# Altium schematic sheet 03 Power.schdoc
size 400 x 277 mm; Device: default420x297; Symbol: default420x297; Name: default420x297; Size: "A3"; Id: /; File: 03 Power; Sheet: /
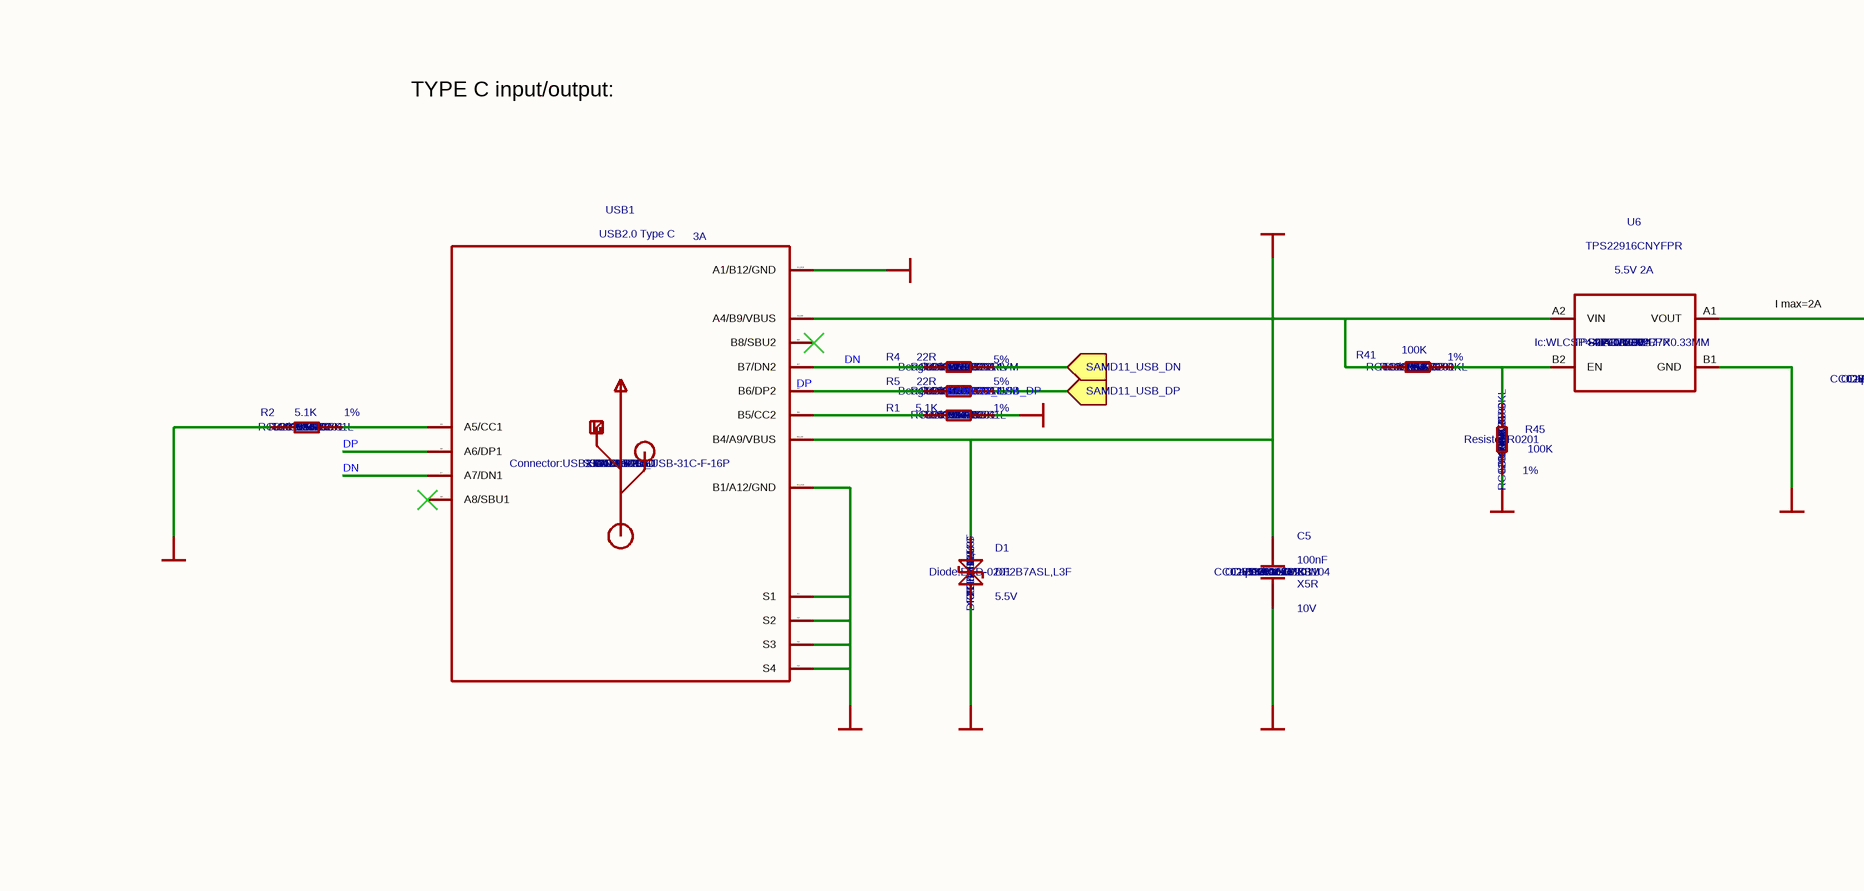
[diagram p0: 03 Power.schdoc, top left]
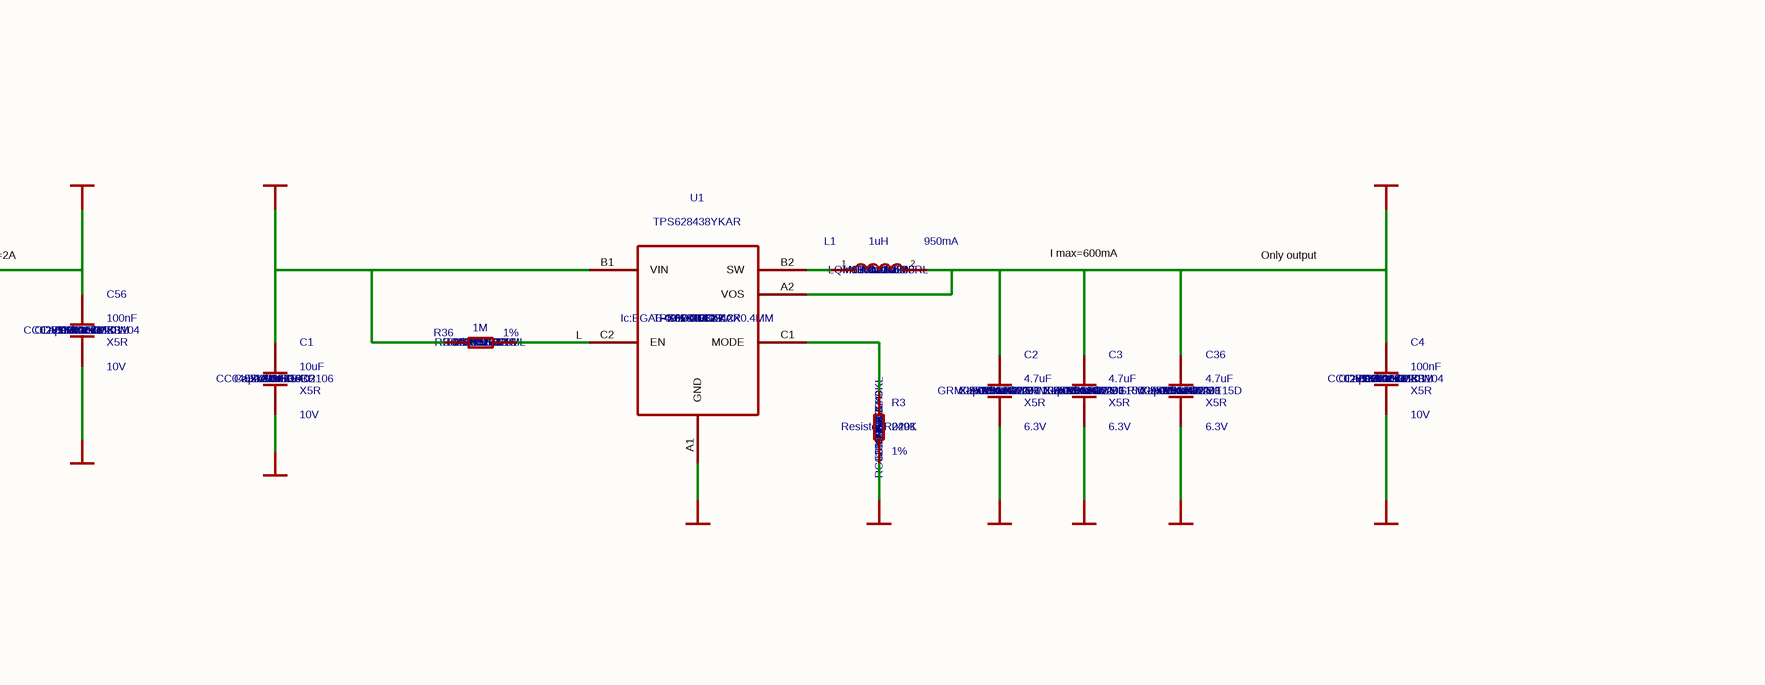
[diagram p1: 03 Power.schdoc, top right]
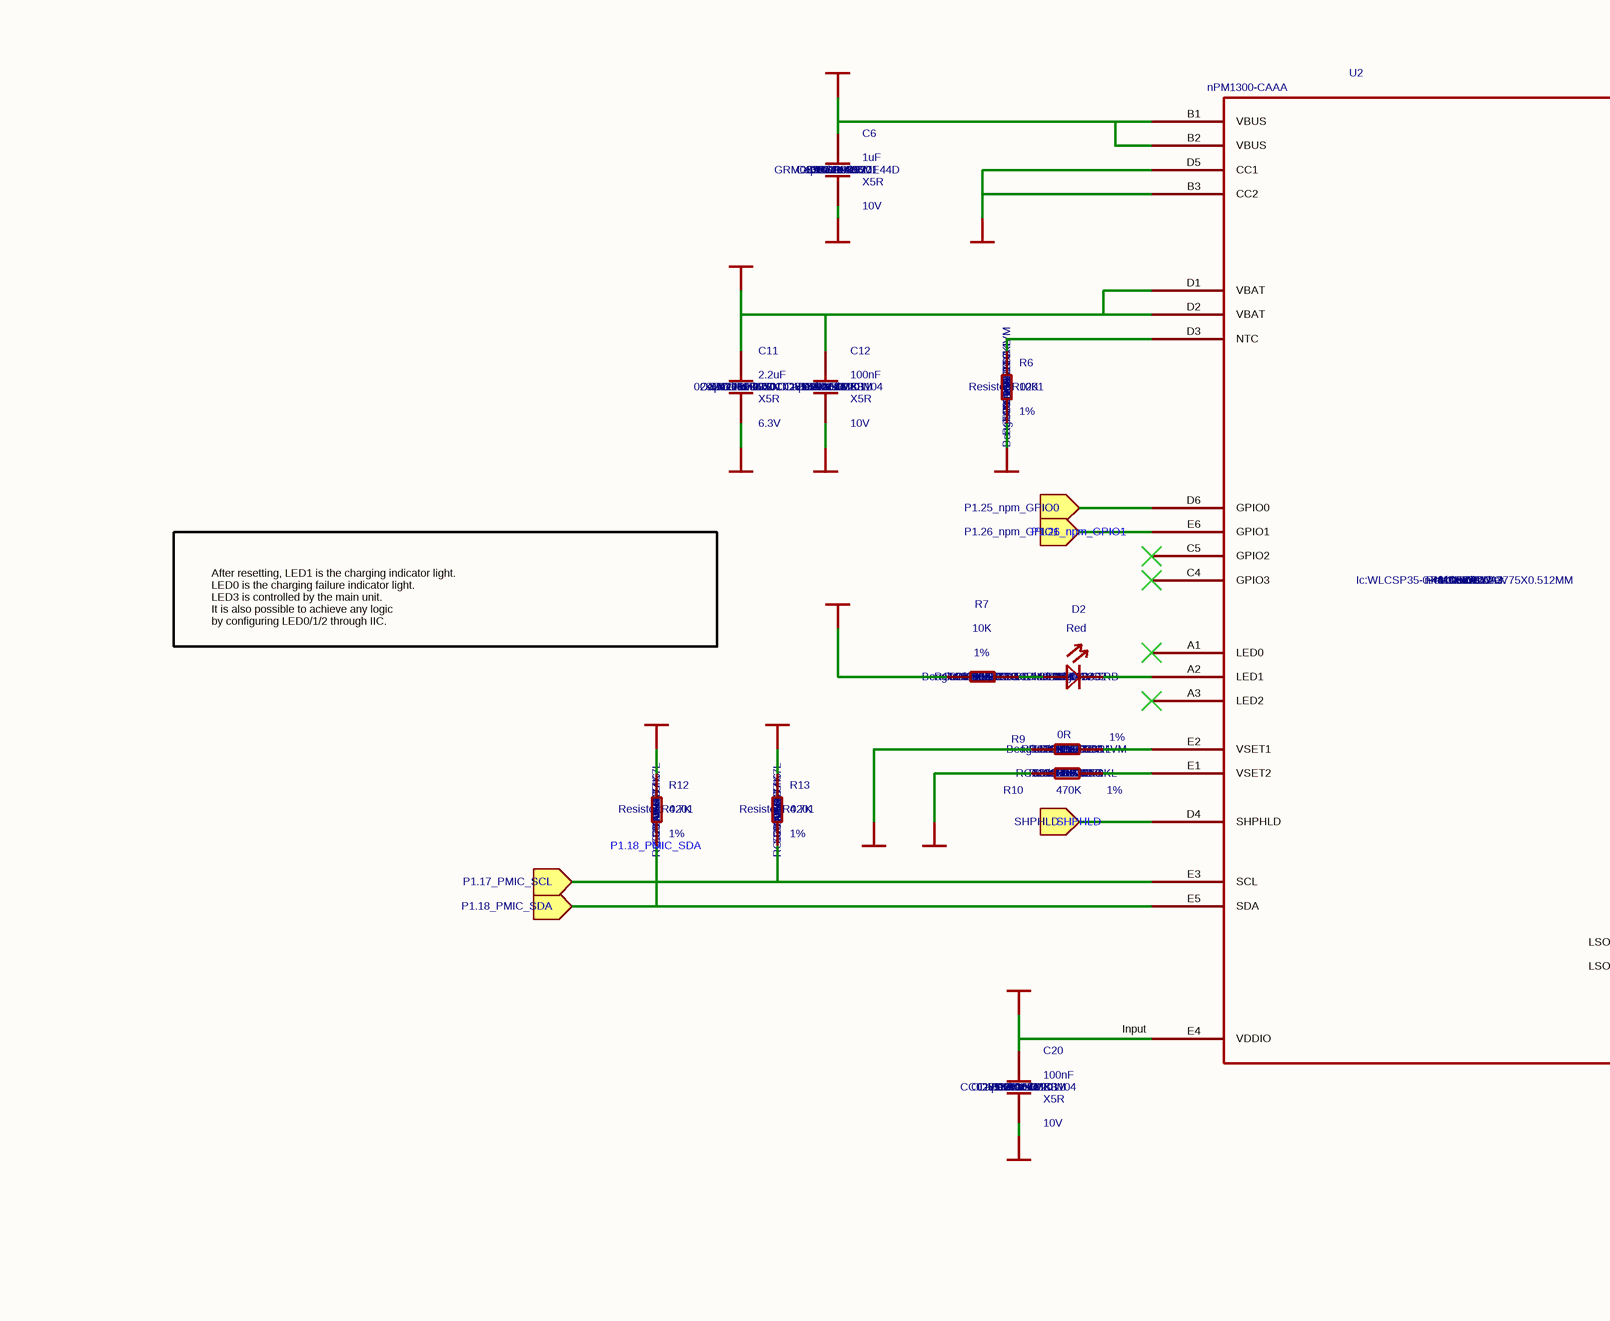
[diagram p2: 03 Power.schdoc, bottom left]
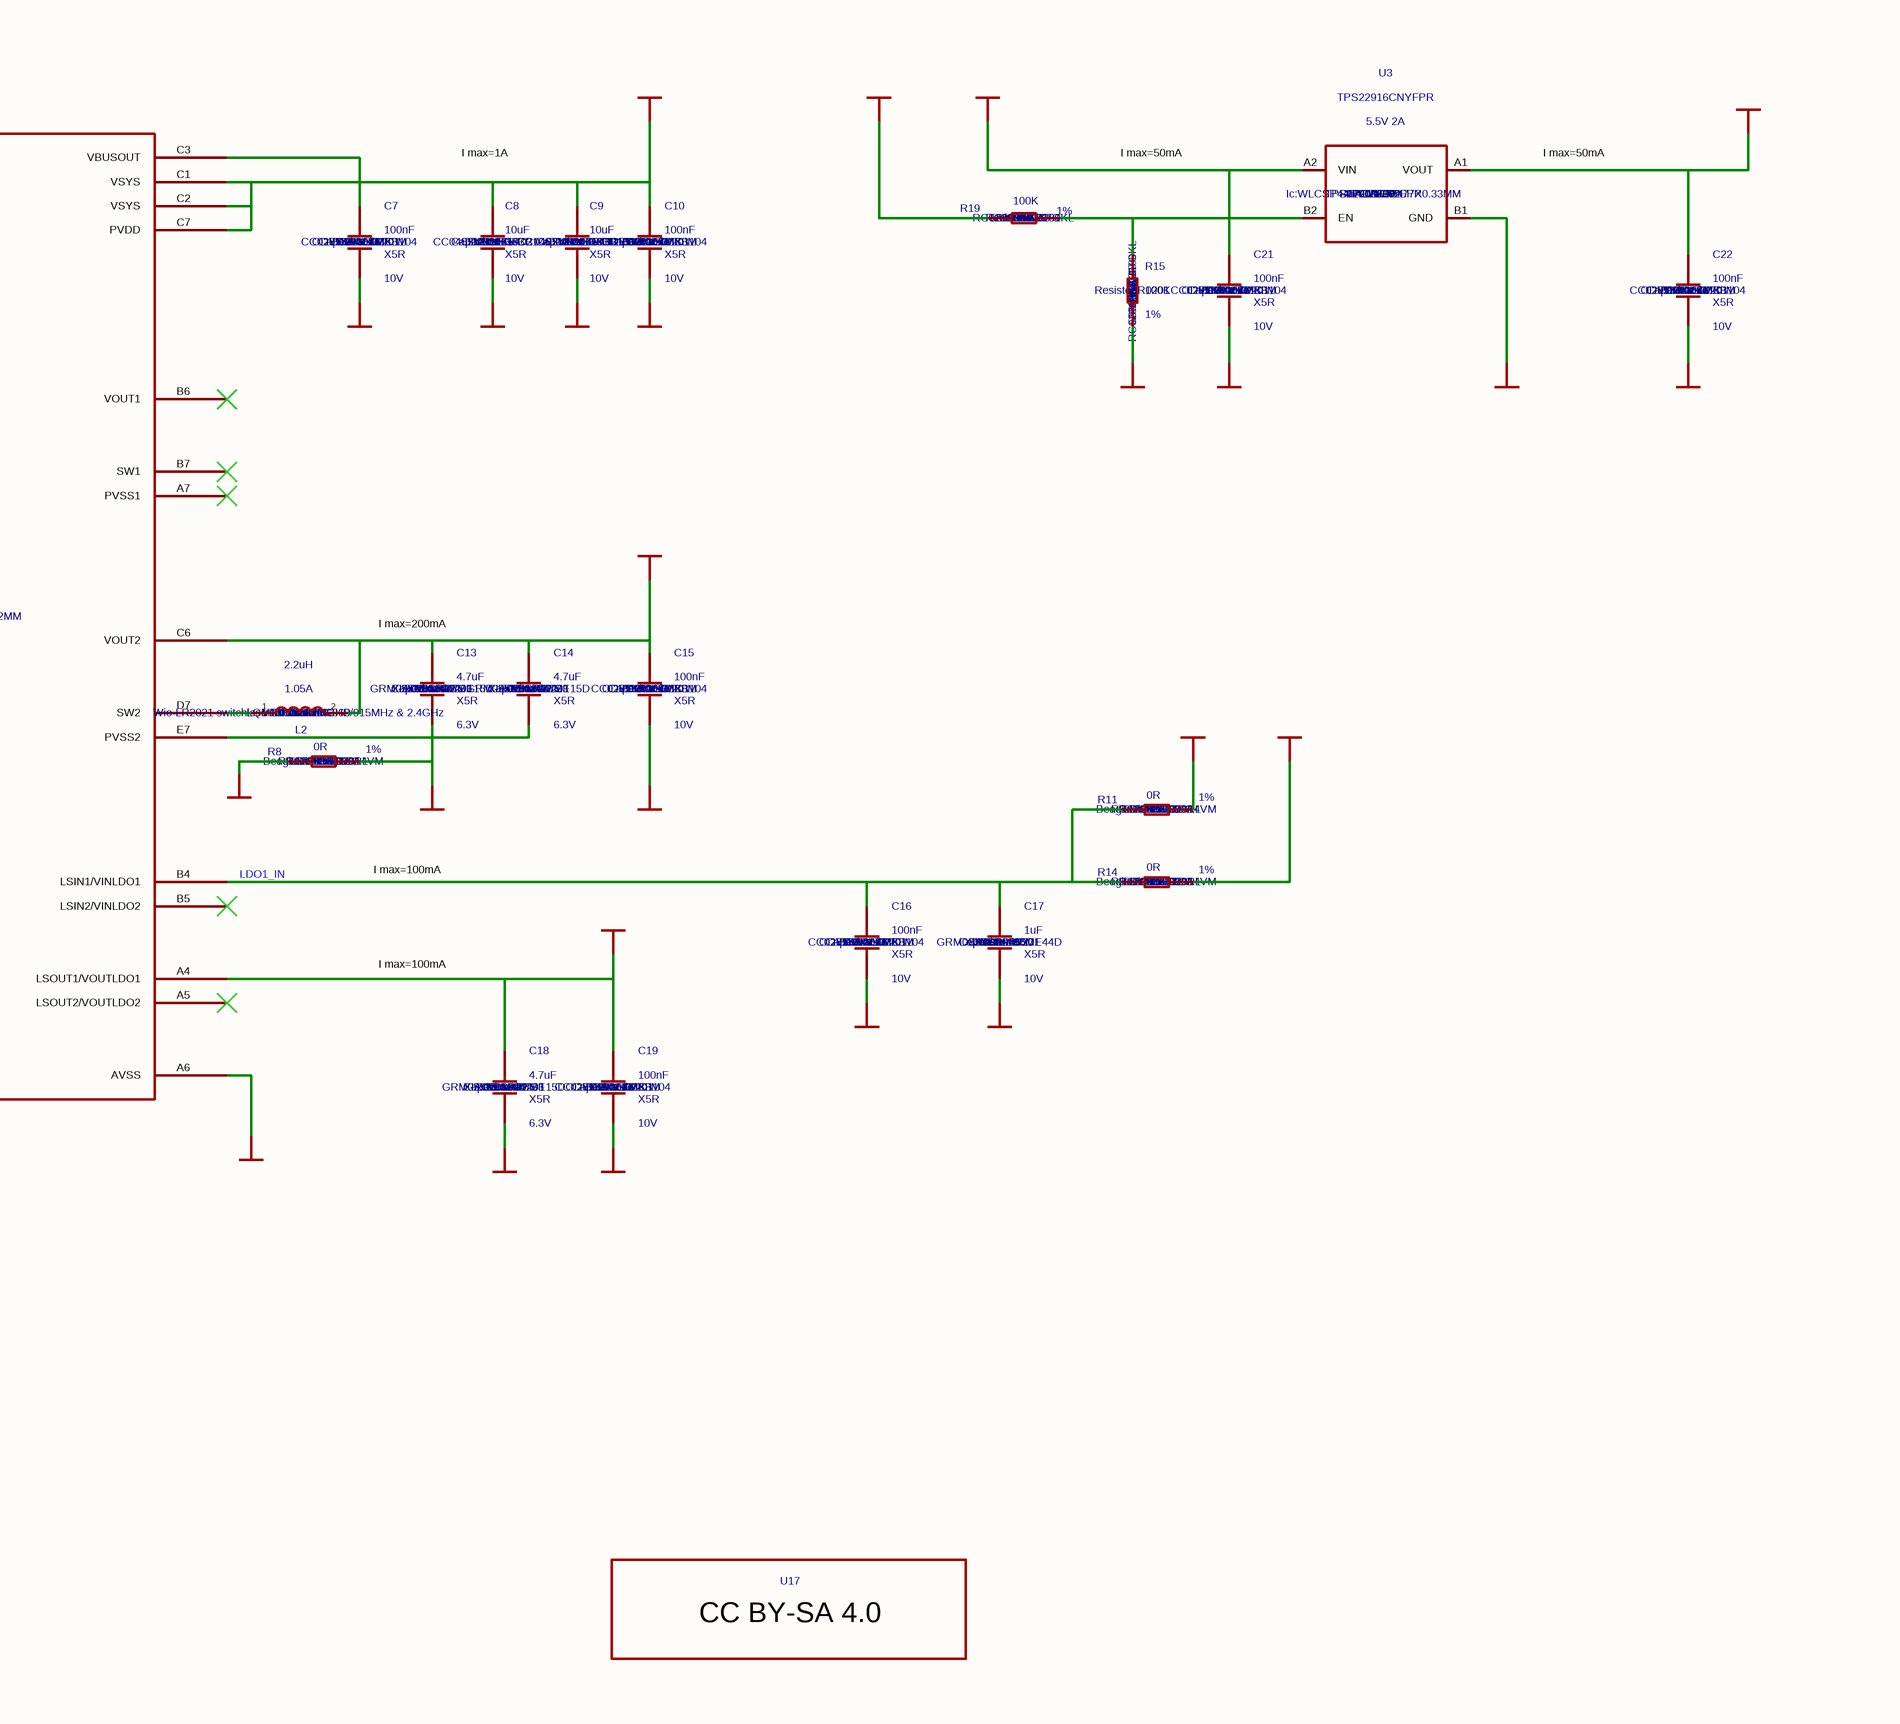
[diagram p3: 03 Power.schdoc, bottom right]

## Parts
C1  value 10uF  Manufacturer: YAGEO  MPN: CC0402MRX5R6BB106  SKU: 302010519  Dielectric: X5R  Voltage Rating: 10V  Status: XIAO  Temperature: -55°C to 85°C  [Capacitor:C0402]  (hidden comment: Seeed_libdb_Capacitors/CA40210UF0-TZJGY3)
C2  value 4.7uF  Manufacturer: Murata  MPN: GRM035R60J475ME15D  SKU: 302013247  Dielectric: X5R  Part Type: Ceramic  Voltage Rating: 6.3V  Status: XIAO ESP32 S3  Temperature: -55°C to 85°C  [Capacitor:C0201]  (hidden comment: Seeed_libdb_Capacitors/CA20147UF0-SN7236)
C3  value 4.7uF  Manufacturer: Murata  MPN: GRM035R60J475ME15D  SKU: 302013247  Dielectric: X5R  Part Type: Ceramic  Voltage Rating: 6.3V  Status: XIAO ESP32 S3  Temperature: -55°C to 85°C  [Capacitor:C0201]  (hidden comment: Seeed_libdb_Capacitors/CA20147UF0-SN7236)
C4  value 100nF  Manufacturer: YAGEO  MPN: CC0201KRX5R6BB104  SKU: 302010271  Dielectric: X5R  Part Type: Ceramic  Voltage Rating: 10V  Status: ODYSSEY-i.MX8M  Temperature: -55°C to 85°C  [Capacitor:C0201]  (hidden comment: Seeed_libdb_Capacitors/CA201100NF-SQS4XQ)
C5  value 100nF  Manufacturer: YAGEO  MPN: CC0201KRX5R6BB104  SKU: 302010271  Dielectric: X5R  Part Type: Ceramic  Voltage Rating: 10V  Status: ODYSSEY-i.MX8M  Temperature: -55°C to 85°C  [Capacitor:C0201]  (hidden comment: Seeed_libdb_Capacitors/CA201100NF-SQS4XQ)
C6  value 1uF  Manufacturer: muRata  MPN: GRM033R61A105ME44D  SKU: 302010730  Dielectric: X5R  Part Type: Ceramic  Voltage Rating: 10V  Status: XIAO RP2350  Temperature: -55°C to 85°C  [Capacitor:C0201]  (hidden comment: Seeed_libdb_Capacitors/CA2011UF00-7ESDY3)
C7  value 100nF  Manufacturer: YAGEO  MPN: CC0201KRX5R6BB104  SKU: 302010271  Dielectric: X5R  Part Type: Ceramic  Voltage Rating: 10V  Status: ODYSSEY-i.MX8M  Temperature: -55°C to 85°C  [Capacitor:C0201]  (hidden comment: Seeed_libdb_Capacitors/CA201100NF-SQS4XQ)
C8  value 10uF  Manufacturer: YAGEO  MPN: CC0402MRX5R6BB106  SKU: 302010519  Dielectric: X5R  Voltage Rating: 10V  Status: XIAO  Temperature: -55°C to 85°C  [Capacitor:C0402]  (hidden comment: Seeed_libdb_Capacitors/CA40210UF0-TZJGY3)
C9  value 10uF  Manufacturer: YAGEO  MPN: CC0402MRX5R6BB106  SKU: 302010519  Dielectric: X5R  Voltage Rating: 10V  Status: XIAO  Temperature: -55°C to 85°C  [Capacitor:C0402]  (hidden comment: Seeed_libdb_Capacitors/CA40210UF0-TZJGY3)
C10  value 100nF  Manufacturer: YAGEO  MPN: CC0201KRX5R6BB104  SKU: 302010271  Dielectric: X5R  Part Type: Ceramic  Voltage Rating: 10V  Status: ODYSSEY-i.MX8M  Temperature: -55°C to 85°C  [Capacitor:C0201]  (hidden comment: Seeed_libdb_Capacitors/CA201100NF-SQS4XQ)
C11  value 2.2uF  Manufacturer: FH  MPN: 0201X225M6R3NT  SKU: 302012960  Dielectric: X5R  Part Type: Ceramic  Voltage Rating: 6.3V  Status: XIAO_RP2350  Temperature: -55°C to 85°C  [Capacitor:C0201]  (hidden comment: Seeed_libdb_Capacitors/CA20122UF0-RZ5XFV)
C12  value 100nF  Manufacturer: YAGEO  MPN: CC0201KRX5R6BB104  SKU: 302010271  Dielectric: X5R  Part Type: Ceramic  Voltage Rating: 10V  Status: ODYSSEY-i.MX8M  Temperature: -55°C to 85°C  [Capacitor:C0201]  (hidden comment: Seeed_libdb_Capacitors/CA201100NF-SQS4XQ)
C13  value 4.7uF  Manufacturer: Murata  MPN: GRM035R60J475ME15D  SKU: 302013247  Dielectric: X5R  Part Type: Ceramic  Voltage Rating: 6.3V  Status: XIAO ESP32 S3  Temperature: -55°C to 85°C  [Capacitor:C0201]  (hidden comment: Seeed_libdb_Capacitors/CA20147UF0-SN7236)
C14  value 4.7uF  Manufacturer: Murata  MPN: GRM035R60J475ME15D  SKU: 302013247  Dielectric: X5R  Part Type: Ceramic  Voltage Rating: 6.3V  Status: XIAO ESP32 S3  Temperature: -55°C to 85°C  [Capacitor:C0201]  (hidden comment: Seeed_libdb_Capacitors/CA20147UF0-SN7236)
C15  value 100nF  Manufacturer: YAGEO  MPN: CC0201KRX5R6BB104  SKU: 302010271  Dielectric: X5R  Part Type: Ceramic  Voltage Rating: 10V  Status: ODYSSEY-i.MX8M  Temperature: -55°C to 85°C  [Capacitor:C0201]  (hidden comment: Seeed_libdb_Capacitors/CA201100NF-SQS4XQ)
C16  value 100nF  Manufacturer: YAGEO  MPN: CC0201KRX5R6BB104  SKU: 302010271  Dielectric: X5R  Part Type: Ceramic  Voltage Rating: 10V  Status: ODYSSEY-i.MX8M  Temperature: -55°C to 85°C  [Capacitor:C0201]  (hidden comment: Seeed_libdb_Capacitors/CA201100NF-SQS4XQ)
C17  value 1uF  Manufacturer: muRata  MPN: GRM033R61A105ME44D  SKU: 302010730  Dielectric: X5R  Part Type: Ceramic  Voltage Rating: 10V  Status: XIAO RP2350  Temperature: -55°C to 85°C  [Capacitor:C0201]  (hidden comment: Seeed_libdb_Capacitors/CA2011UF00-7ESDY3)
C18  value 4.7uF  Manufacturer: Murata  MPN: GRM035R60J475ME15D  SKU: 302013247  Dielectric: X5R  Part Type: Ceramic  Voltage Rating: 6.3V  Status: XIAO ESP32 S3  Temperature: -55°C to 85°C  [Capacitor:C0201]  (hidden comment: Seeed_libdb_Capacitors/CA20147UF0-SN7236)
C19  value 100nF  Manufacturer: YAGEO  MPN: CC0201KRX5R6BB104  SKU: 302010271  Dielectric: X5R  Part Type: Ceramic  Voltage Rating: 10V  Status: ODYSSEY-i.MX8M  Temperature: -55°C to 85°C  [Capacitor:C0201]  (hidden comment: Seeed_libdb_Capacitors/CA201100NF-SQS4XQ)
C20  value 100nF  Manufacturer: YAGEO  MPN: CC0201KRX5R6BB104  SKU: 302010271  Dielectric: X5R  Part Type: Ceramic  Voltage Rating: 10V  Status: ODYSSEY-i.MX8M  Temperature: -55°C to 85°C  [Capacitor:C0201]  (hidden comment: Seeed_libdb_Capacitors/CA201100NF-SQS4XQ)
C21  value 100nF  Manufacturer: YAGEO  MPN: CC0201KRX5R6BB104  SKU: 302010271  Dielectric: X5R  Part Type: Ceramic  Voltage Rating: 10V  Status: ODYSSEY-i.MX8M  Temperature: -55°C to 85°C  [Capacitor:C0201]  (hidden comment: Seeed_libdb_Capacitors/CA201100NF-SQS4XQ)
C22  value 100nF  Manufacturer: YAGEO  MPN: CC0201KRX5R6BB104  SKU: 302010271  Dielectric: X5R  Part Type: Ceramic  Voltage Rating: 10V  Status: ODYSSEY-i.MX8M  Temperature: -55°C to 85°C  [Capacitor:C0201]  (hidden comment: Seeed_libdb_Capacitors/CA201100NF-SQS4XQ)
C36  value 4.7uF  Manufacturer: Murata  MPN: GRM035R60J475ME15D  SKU: 302013247  Dielectric: X5R  Part Type: Ceramic  Voltage Rating: 6.3V  Status: XIAO ESP32 S3  Temperature: -55°C to 85°C  [Capacitor:C0201]  (hidden comment: Seeed_libdb_Capacitors/CA20147UF0-SN7236)
C56  value 100nF  Manufacturer: YAGEO  MPN: CC0201KRX5R6BB104  SKU: 302010271  Dielectric: X5R  Part Type: Ceramic  Voltage Rating: 10V  Status: ODYSSEY-i.MX8M  Temperature: -55°C to 85°C  [Capacitor:C0201]  (hidden comment: Seeed_libdb_Capacitors/CA201100NF-SQS4XQ)
D1  value DF2B7ASL,L3F  Manufacturer: TOSHIBA  SKU: 304060494  Part Type: ESD  Rating: 5.5V  Temperature: -40°C to 125°C  [Diode:ESD-0201]  (hidden comment: Seeed_libdb_Diode/DI201DF2B7-5S4UTU)
D2  value Red  Manufacturer: Bright  MPN: BL-HUB37A-AV-TRB  SKU: 304090122  Part Type: LED  Status: ST  Temperature: -40°C to 85°C  [Diode:LED-0402]  (hidden comment: Seeed_libdb_Diode/DI402RED00-UPJYSL)
L1  value 1uH  Manufacturer: Murata  MPN: LQM18PN1R0MFRL  SKU: 303011855  Part Type: Inductor  Rating: 950mA  Status: XIAO MG24  [Inductor:L0603]  (hidden comment: Seeed_libdb_Inductor/IN6031UH00-J6SDNV)
L2  value 2.2uH  Manufacturer: murata  MPN: LQM18PN2R2MGHD  SKU: 303012198  Part Type: Inductor  Rating: 1.05A  Status: Wio-LR2021 switchless RF Module - 868/915MHz & 2.4GHz  Temperature: -40°C to 85°C  [Inductor:L0603]  (hidden comment: Seeed_libdb_Inductor/IN60322UH0-SK3TYP)
R1  value 5.1K  Manufacturer: YAGEO  MPN: RC0201FR-075K1L  SKU: 301010885  Tolerance: 1%  Part Type: RES  Status: XIAO  Temperature: -55°C to 125°C  [Resistor:R0201]  (hidden comment: Seeed_libdb_Resistors/RE20151K00-NKWZEY)
R2  value 5.1K  Manufacturer: YAGEO  MPN: RC0201FR-075K1L  SKU: 301010885  Tolerance: 1%  Part Type: RES  Status: XIAO  Temperature: -55°C to 125°C  [Resistor:R0201]  (hidden comment: Seeed_libdb_Resistors/RE20151K00-NKWZEY)
R3  value 249K  Manufacturer: YAGEO  MPN: RC0201FR-07249KL  SKU: 301013554  Tolerance: 1%  Part Type: RES  Status: XIAO  Temperature: -55°C to 125°C  [Resistor:R0201]  (hidden comment: Seeed_libdb_Resistors/RE201249K0-VLD8UD)
R4  value 22R  Manufacturer: YAGEO  MPN: RC0201JR-0722RL  SKU: 301010789  Tolerance: 5%  Part Type: RES  Status: BeagleBone AI TDA4VM  Temperature: -55°C to 125°C  [Resistor:R0201]  (hidden comment: Seeed_libdb_Resistors/RE20122R00-QTYGK6)
R5  value 22R  Manufacturer: YAGEO  MPN: RC0201JR-0722RL  SKU: 301010789  Tolerance: 5%  Part Type: RES  Status: BeagleBone AI TDA4VM  Temperature: -55°C to 125°C  [Resistor:R0201]  (hidden comment: Seeed_libdb_Resistors/RE20122R00-QTYGK6)
R6  value 10K  Manufacturer: YAGEO  MPN: RC0201FR-0710KL  SKU: 301010526  Tolerance: 1%  Part Type: RES  Status: BeagleBone AI TDA4VM  Temperature: -55°C to 125°C  [Resistor:R0201]  (hidden comment: Seeed_libdb_Resistors/RE20110K00-N6CP3B)
R7  value 10K  Manufacturer: YAGEO  MPN: RC0201FR-0710KL  SKU: 301010526  Tolerance: 1%  Part Type: RES  Status: BeagleBone AI TDA4VM  Temperature: -55°C to 125°C  [Resistor:R0201]  (hidden comment: Seeed_libdb_Resistors/RE20110K00-N6CP3B)
R8  value 0R  Manufacturer: YAGEO  MPN: RC0201FR-070RL  SKU: 301010525  Tolerance: 1%  Part Type: RES  Status: BeagleBone AI TDA4VM  Temperature: -55°C to 125°C  [Resistor:R0201]  (hidden comment: Seeed_libdb_Resistors/RE2010R000-2FV3F9)
R9  value 0R  Manufacturer: YAGEO  MPN: RC0201FR-070RL  SKU: 301010525  Tolerance: 1%  Part Type: RES  Status: BeagleBone AI TDA4VM  Temperature: -55°C to 125°C  [Resistor:R0201]  (hidden comment: Seeed_libdb_Resistors/RE2010R000-2FV3F9)
R10  value 470K  Manufacturer: YAGEO  MPN: RC0201FR-07470KL  SKU: 301010764  Tolerance: 1%  Part Type: RES  Status: XIAO RP2350  Temperature: -55°C to 125°C  [Resistor:R0201]  (hidden comment: Seeed_libdb_Resistors/RE201470K0-CH9MKE)
R11  value 0R  Manufacturer: YAGEO  MPN: RC0201FR-070RL  SKU: 301010525  Tolerance: 1%  Part Type: RES  Status: BeagleBone AI TDA4VM  Temperature: -55°C to 125°C  [Resistor:R0201]  (hidden comment: Seeed_libdb_Resistors/RE2010R000-2FV3F9)
R12  value 4.7K  Manufacturer: YAGEO  MPN: RC0201JR-074K7L  SKU: 301010677  Tolerance: 1%  Part Type: RES  Status: XIAO  Temperature: -55°C to 125°C  [Resistor:R0201]  (hidden comment: Seeed_libdb_Resistors/RE20147K00-2N4EPM)
R13  value 4.7K  Manufacturer: YAGEO  MPN: RC0201JR-074K7L  SKU: 301010677  Tolerance: 1%  Part Type: RES  Status: XIAO  Temperature: -55°C to 125°C  [Resistor:R0201]  (hidden comment: Seeed_libdb_Resistors/RE20147K00-2N4EPM)
R14  value 0R  Manufacturer: YAGEO  MPN: RC0201FR-070RL  SKU: 301010525  Tolerance: 1%  Part Type: RES  Status: BeagleBone AI TDA4VM  Temperature: -55°C to 125°C  [Resistor:R0201]  (hidden comment: Seeed_libdb_Resistors/RE2010R000-2FV3F9)
R15  value 100K  Manufacturer: YAGEO  MPN: RC0201FR-07100KL  SKU: 301010765  Tolerance: 1%  Part Type: RES  Status: XIAO  Temperature: -55°C to 125°C  [Resistor:R0201]  (hidden comment: Seeed_libdb_Resistors/RE201100K0-XFHWYX)
R19  value 100K  Manufacturer: YAGEO  MPN: RC0201FR-07100KL  SKU: 301010765  Tolerance: 1%  Part Type: RES  Status: XIAO  Temperature: -55°C to 125°C  [Resistor:R0201]  (hidden comment: Seeed_libdb_Resistors/RE201100K0-XFHWYX)
R36  value 1M  Manufacturer: YAGEO  MPN: RC0201FR-071ML  SKU: 301012633  Tolerance: 1%  Part Type: RES  Status: XIAO BLE  Temperature: -55°C to 125°C  [Resistor:R0201]  (hidden comment: Seeed_libdb_Resistors/RE2011M000-4DW8S5)
R41  value 100K  Manufacturer: YAGEO  MPN: RC0201FR-07100KL  SKU: 301010765  Tolerance: 1%  Part Type: RES  Status: XIAO  Temperature: -55°C to 125°C  [Resistor:R0201]  (hidden comment: Seeed_libdb_Resistors/RE201100K0-XFHWYX)
R45  value 100K  Manufacturer: YAGEO  MPN: RC0201FR-07100KL  SKU: 301010765  Tolerance: 1%  Part Type: RES  Status: XIAO  Temperature: -55°C to 125°C  [Resistor:R0201]  (hidden comment: Seeed_libdb_Resistors/RE201100K0-XFHWYX)
U1  value TPS628438YKAR  Manufacturer: TI  SKU: 310033052  Part Type: DCDC  Status: XIAO MG24  Temperature: -40°C to 125°C  [Ic:BGA6-0.35-0.85X1.2X0.4MM]  (hidden comment: Seeed_libdb_Ic/ICB60TPS62-UCFRKF)
U2  value nPM1300-CAAA  Manufacturer: Nordic  SKU: 310032912  Part Type: IC  Status: Pebble Watcher  Temperature: -40°C to 125°C  Priority: None  [Ic:WLCSP35-0.44-3.0775X2.3775X0.512MM]  (hidden comment: Seeed_libdb_Ic/IC775NPM13-D9AN38)
U3  value TPS22916CNYFPR  Manufacturer: TI  SKU: 310032992  Part Type: POWER  Rating: 5.5V 2A  Status: XIAO MG24  Temperature: -40°C to 85°C  Priority: A  [Ic:WLCSP4-0.4-0.77X0.77X0.33MM]  (hidden comment: Seeed_libdb_Ic/IC400TPS22-ASPV86)
U6  value TPS22916CNYFPR  Manufacturer: TI  SKU: 310032992  Part Type: POWER  Rating: 5.5V 2A  Status: XIAO MG24  Temperature: -40°C to 85°C  Priority: A  [Ic:WLCSP4-0.4-0.77X0.77X0.33MM]  (hidden comment: Seeed_libdb_Ic/IC400TPS22-ASPV86)
U17  Misc_LOGO_CC_BY-SA_4.0  [Misc:LOGO_CC_BY-SA_4.0]  (value not drawn)
USB1  value USB2.0 Type C  Manufacturer: SUNGTECH  MPN: ST-USB-3316T  SKU: 320011419  Part Type: Connector  Rating: 3A  Status: XIAO RP2350  Temperature: -30°C to 85°C  [Connector:USB2.0-TYPE-C_USB-31C-F-16P]  (hidden comment: Seeed_libdb_Connector/CN200USB20-9E72RK)

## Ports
P1.17_PMIC_SCL (in), P1.18_PMIC_SDA (in), P1.25_npm_GPIO0 (in), P1.26_npm_GPIO1 (in), SAMD11_USB_DN (in), SAMD11_USB_DP (in), SHPHLD (in)

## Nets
power_+5V: C1.1 C2.1 C3.1 C4.1 C5.1 C6.1 C8.1 C9.1 C10.1 C11.1 C12.1 C13.1 C14.1 C15.1 C18.1 C19.1 C20.1 C21.1 C22.1 C36.1 C56.1 D1.2 L1.2 L2.2 R7.1 R11.2 R12.2 R13.2 R14.2 R19.2 R36.2 R41.2 U1.A2(VOS) U1.B1(VIN) U2.A4(LSOUT1/VOUTLDO1) U2.B1(VBUS) U2.B2(VBUS) U2.C1(VSYS) U2.C2(VSYS) U2.C6(VOUT2) U2.C7(PVDD) U2.D1(VBAT) U2.D2(VBAT) U2.E4(VDDIO) U3.A1(VOUT) U3.A2(VIN) U6.A1(VOUT) U6.A2(VIN) USB1.A4_B9(A4/B9/VBUS) USB1.B4_A9(B4/A9/VBUS)
Power_Gnd_GNDREF: C1.2 C2.2 C3.2 C4.2 C5.2 C6.2 C7.2 C8.2 C9.2 C10.2 C11.2 C12.2 C13.2 C14.2 C15.2 C16.2 C17.2 C18.2 C19.2 C20.2 C21.2 C22.2 C36.2 C56.2 D1.1 R1.2 R2.1 R3.1 R6.1 R8.1 R8.2 R9.1 R10.1 R15.1 R45.2 U1.A1(GND) U2.A6(AVSS) U2.B3(CC2) U2.D5(CC1) U2.E7(PVSS2) U3.B1(GND) U6.B1(GND) USB1.A1_B12(A1/B12/GND) USB1.B1_A12(B1/A12/GND) USB1.S1 USB1.S2 USB1.S3 USB1.S4
DN: R4.1 USB1.A7(A7/DN1) USB1.B7(B7/DN2)
DP: R5.1 USB1.A6(A6/DP1) USB1.B6(B6/DP2)
LDO1_IN: C16.1 C17.1 R11.1 R14.1 U2.B4(LSIN1/VINLDO1)
P1.17_PMIC_SCL: R13.1 U2.E3(SCL) ; port P1.17_PMIC_SCL
P1.18_PMIC_SDA: R12.1 U2.E5(SDA) ; port P1.18_PMIC_SDA
P1.25_npm_GPIO0: U2.D6(GPIO0) ; port P1.25_npm_GPIO0
P1.26_npm_GPIO1: U2.E6(GPIO1) ; port P1.26_npm_GPIO1
SAMD11_USB_DN: R4.2 ; port SAMD11_USB_DN
SAMD11_USB_DP: R5.2 ; port SAMD11_USB_DP
SHPHLD: U2.D4(SHPHLD) ; port SHPHLD
NetC7_1: C7.1 U2.C3(VBUSOUT)
NetD2_1: D2.1(+) R7.2
NetD2_2: D2.2(-) U2.A2(LED1)
NetL1_1: L1.1 U1.B2(SW)
NetL2_1: L2.1 U2.D7(SW2)
NetR1_1: R1.1 USB1.B5(B5/CC2)
NetR2_2: R2.2 USB1.A5(A5/CC1)
NetR3_2: R3.2 U1.C1(MODE)
NetR6_2: R6.2 U2.D3(NTC)
NetR9_2: R9.2 U2.E2(VSET1)
NetR10_2: R10.2 U2.E1(VSET2)
NetR15_2: R15.2 R19.1 U3.B2(EN)
NetR36_1: R36.1 U1.C2(EN)
NetR41_1: R41.1 R45.1 U6.B2(EN)

Not connected (* = marked no-connect by the designer): U2 A1(LED0)* A3(LED2)* A5(LSOUT2/VOUTLDO2)* A7(PVSS1)* B5(LSIN2/VINLDO2)* B6(VOUT1)* B7(SW1)* C4(GPIO3)* C5(GPIO2)*; USB1 A8(A8/SBU1)* B8(B8/SBU2)*

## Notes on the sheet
- TYPE C input/output:
- I max=2A
- I max=600mA
- Only output
- L
- I max=1A
- I max=50mA
- After resetting, LED1 is the charging indicator light.
  LED0 is the charging failure indicator light.
  LED3 is controlled by the main unit.
  It is also possible to achieve any logic
  by configuring LED0/1/2 through IIC.
- (near C13) I max=200mA
- I max=100mA
- Input

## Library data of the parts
C1 = Seeed_libdb_Capacitors/CA40210UF0-TZJGY3: SMD CAP Ceramic 10uF-10V-20%-X5R;0402; UniqueId: b4693cfd16d534cd; AddInBom: yes
C2 = Seeed_libdb_Capacitors/CA20147UF0-SN7236: SMD CAP Ceramic 4.7uF-6.3V-20%-X5R;0201; UniqueId: a2c5d49bc5dde298; AddInBom: yes
C3 = Seeed_libdb_Capacitors/CA20147UF0-SN7236: SMD CAP Ceramic 4.7uF-6.3V-20%-X5R;0201; UniqueId: cc82bf2c2e22e605; AddInBom: yes
C4 = Seeed_libdb_Capacitors/CA201100NF-SQS4XQ: SMD CAP Ceramic 100nF-10V-10%-X5R;0201; UniqueId: 3a68d3ddabf48558; AddInBom: yes
C5 = Seeed_libdb_Capacitors/CA201100NF-SQS4XQ: SMD CAP Ceramic 100nF-10V-10%-X5R;0201; UniqueId: ddba3c46cf8b8e66; AddInBom: yes
C6 = Seeed_libdb_Capacitors/CA2011UF00-7ESDY3: SMD CAP Ceramic 1uF-10V-20%-X5R;0201; UniqueId: ab4a8fe24fad9fe4; AddInBom: yes
C7 = Seeed_libdb_Capacitors/CA201100NF-SQS4XQ: SMD CAP Ceramic 100nF-10V-10%-X5R;0201; UniqueId: 48d2dd422533522c; AddInBom: yes
C8 = Seeed_libdb_Capacitors/CA40210UF0-TZJGY3: SMD CAP Ceramic 10uF-10V-20%-X5R;0402; UniqueId: 80f3708378e3d903; AddInBom: yes
C9 = Seeed_libdb_Capacitors/CA40210UF0-TZJGY3: SMD CAP Ceramic 10uF-10V-20%-X5R;0402; UniqueId: 7ddfd2f632a8b17d; AddInBom: yes
C10 = Seeed_libdb_Capacitors/CA201100NF-SQS4XQ: SMD CAP Ceramic 100nF-10V-10%-X5R;0201; UniqueId: 3e75135af30e0f04; AddInBom: yes
C11 = Seeed_libdb_Capacitors/CA20122UF0-RZ5XFV: SMD CAP Ceramic 2.2uF-6.3V-20%-X5R;0201; UniqueId: 20764de07767b3a1; AddInBom: yes
C12 = Seeed_libdb_Capacitors/CA201100NF-SQS4XQ: SMD CAP Ceramic 100nF-10V-10%-X5R;0201; UniqueId: 26a39bcafcc8ce7c; AddInBom: yes
C13 = Seeed_libdb_Capacitors/CA20147UF0-SN7236: SMD CAP Ceramic 4.7uF-6.3V-20%-X5R;0201; UniqueId: e7ba3aba9f9889c8; AddInBom: yes
C14 = Seeed_libdb_Capacitors/CA20147UF0-SN7236: SMD CAP Ceramic 4.7uF-6.3V-20%-X5R;0201; UniqueId: 00361082df9d4549; AddInBom: yes
C15 = Seeed_libdb_Capacitors/CA201100NF-SQS4XQ: SMD CAP Ceramic 100nF-10V-10%-X5R;0201; UniqueId: 86bb77bda672094d; AddInBom: yes
C16 = Seeed_libdb_Capacitors/CA201100NF-SQS4XQ: SMD CAP Ceramic 100nF-10V-10%-X5R;0201; UniqueId: c8e923f96b539988; AddInBom: yes
C17 = Seeed_libdb_Capacitors/CA2011UF00-7ESDY3: SMD CAP Ceramic 1uF-10V-20%-X5R;0201; UniqueId: 48700c84863a802e; AddInBom: yes
C18 = Seeed_libdb_Capacitors/CA20147UF0-SN7236: SMD CAP Ceramic 4.7uF-6.3V-20%-X5R;0201; UniqueId: d9d0285421fe3ef0; AddInBom: yes
C19 = Seeed_libdb_Capacitors/CA201100NF-SQS4XQ: SMD CAP Ceramic 100nF-10V-10%-X5R;0201; UniqueId: 9b75bd895f0e39d2; AddInBom: yes
C20 = Seeed_libdb_Capacitors/CA201100NF-SQS4XQ: SMD CAP Ceramic 100nF-10V-10%-X5R;0201; UniqueId: 97d7532320e593d5; AddInBom: yes
C21 = Seeed_libdb_Capacitors/CA201100NF-SQS4XQ: SMD CAP Ceramic 100nF-10V-10%-X5R;0201; UniqueId: 0259cc883dd91c7a; AddInBom: yes
C22 = Seeed_libdb_Capacitors/CA201100NF-SQS4XQ: SMD CAP Ceramic 100nF-10V-10%-X5R;0201; UniqueId: 7f35450ac3171d20; AddInBom: yes
C36 = Seeed_libdb_Capacitors/CA20147UF0-SN7236: SMD CAP Ceramic 4.7uF-6.3V-20%-X5R;0201; UniqueId: 3db1f6a400993974; AddInBom: yes
C56 = Seeed_libdb_Capacitors/CA201100NF-SQS4XQ: SMD CAP Ceramic 100nF-10V-10%-X5R;0201; UniqueId: a22d741cda083e99; AddInBom: yes
D1 = Seeed_libdb_Diode/DI201DF2B7-5S4UTU: SMD Diode ESD 5.5V-6V-12pF-30KV-30KV;X1SON(2); UniqueId: 6eb2f7ba7a12821c; AddInBom: yes
D2 = Seeed_libdb_Diode/DI402RED00-UPJYSL: SMD LED Clear-Red;0402; UniqueId: cca08e5caf06c018; AddInBom: yes
L1 = Seeed_libdb_Inductor/IN6031UH00-J6SDNV: SMD Inductor;1uH-20%-950mA;0603; UniqueId: d450ceac7adb81c3; AddInBom: yes
L2 = Seeed_libdb_Inductor/IN60322UH0-SK3TYP: SMD Inductor 2.2uH±20%-1.05A;0603; UniqueId: 3f6ee2b1a34b017f; AddInBom: yes
R1 = Seeed_libdb_Resistors/RE20151K00-NKWZEY: SMD RES 5.1K-1%-1/20W;0201; UniqueId: 353b166cc2dee846; AddInBom: yes
R2 = Seeed_libdb_Resistors/RE20151K00-NKWZEY: SMD RES 5.1K-1%-1/20W;0201; UniqueId: 6f63fc6711cfa315; AddInBom: yes
R3 = Seeed_libdb_Resistors/RE201249K0-VLD8UD: SMD RES 249K-1%-1/20W;0201; UniqueId: fe89d0632cfce75f; AddInBom: yes
R4 = Seeed_libdb_Resistors/RE20122R00-QTYGK6: SMD RES 22R-5%-1/20W;0201; UniqueId: fdc86a4b576d9e98; AddInBom: yes
R5 = Seeed_libdb_Resistors/RE20122R00-QTYGK6: SMD RES 22R-5%-1/20W;0201; UniqueId: 9cdd622c9eeecfe7; AddInBom: yes
R6 = Seeed_libdb_Resistors/RE20110K00-N6CP3B: SMD RES 10K-±1%-1/20W;0201; UniqueId: e06ccd13940482ac; AddInBom: yes
R7 = Seeed_libdb_Resistors/RE20110K00-N6CP3B: SMD RES 10K-±1%-1/20W;0201; UniqueId: ba2c6d155e7fd301; AddInBom: yes
R8 = Seeed_libdb_Resistors/RE2010R000-2FV3F9: SMD RES 0R-±1%-1/20W;0201; UniqueId: 86d447fa2a9c8586; AddInBom: yes
R9 = Seeed_libdb_Resistors/RE2010R000-2FV3F9: SMD RES 0R-±1%-1/20W;0201; UniqueId: 1e1ffada38203b9e; AddInBom: yes
R10 = Seeed_libdb_Resistors/RE201470K0-CH9MKE: SMD RES 470K-1%-1/20W;0201; UniqueId: 41bc0941336b1513; AddInBom: yes
R11 = Seeed_libdb_Resistors/RE2010R000-2FV3F9: SMD RES 0R-±1%-1/20W;0201; UniqueId: 763cf8d5648cb4fd; AddInBom: yes
R12 = Seeed_libdb_Resistors/RE20147K00-2N4EPM: SMD RES;4.7K-5%-1/20W;0201; UniqueId: 15ac9218146e0f4b; AddInBom: yes
R13 = Seeed_libdb_Resistors/RE20147K00-2N4EPM: SMD RES;4.7K-5%-1/20W;0201; UniqueId: ff4077a9ca69db92; AddInBom: yes
R14 = Seeed_libdb_Resistors/RE2010R000-2FV3F9: SMD RES 0R-±1%-1/20W;0201; UniqueId: 8b54177fc4d64d35; AddInBom: yes
R15 = Seeed_libdb_Resistors/RE201100K0-XFHWYX: SMD RES 100K-±1%-1/20W;0201; UniqueId: feece054417b9159; AddInBom: yes
R19 = Seeed_libdb_Resistors/RE201100K0-XFHWYX: SMD RES 100K-±1%-1/20W;0201; UniqueId: a32210a39874d8f8; AddInBom: yes
R36 = Seeed_libdb_Resistors/RE2011M000-4DW8S5: SMD RES 1MR-1%-1/20W;0201; UniqueId: ee084f684bde39fa; AddInBom: yes
R41 = Seeed_libdb_Resistors/RE201100K0-XFHWYX: SMD RES 100K-±1%-1/20W;0201; UniqueId: e262797b4e338b99; AddInBom: yes
R45 = Seeed_libdb_Resistors/RE201100K0-XFHWYX: SMD RES 100K-±1%-1/20W;0201; UniqueId: fe3640da4f52432f; AddInBom: yes
U1 = Seeed_libdb_Ic/ICB60TPS62-UCFRKF: SMD IC PMIC;DCDC Buck-600mA,Vin 1.8V to 5.5V,Vout 1.8V to 3.6V;DSBGA; UniqueId: 1bdc0ab44f99f92d; AddInBom: yes
U2 = Seeed_libdb_Ic/IC775NPM13-D9AN38: SMD IC PMIC;WLCSP-35;3.1*2.4mm; UniqueId: 48f0ae2437312dae; AddInBom: yes
U3 = Seeed_libdb_Ic/IC400TPS22-ASPV86: SMD IC PMIC;Power Switch 5.5V2A;WLCSP-4-0.78*0.78mm; UniqueId: 66797bcd97f4f6c2; AddInBom: yes
U6 = Seeed_libdb_Ic/IC400TPS22-ASPV86: SMD IC PMIC;Power Switch 5.5V2A;WLCSP-4-0.78*0.78mm; UniqueId: 124c013cfc851acc; AddInBom: yes
U17 = Misc_LOGO_CC_BY-SA_4.0: UniqueId: 1a5dee1823ef113a; AddInBom: yes
USB1 = Seeed_libdb_Connector/CN200USB20-9E72RK: SMD USB TYPE C-W/P;12+4P-7.35*8.94*3.25mm; UniqueId: 6d6dae296b8b38a5; AddInBom: yes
